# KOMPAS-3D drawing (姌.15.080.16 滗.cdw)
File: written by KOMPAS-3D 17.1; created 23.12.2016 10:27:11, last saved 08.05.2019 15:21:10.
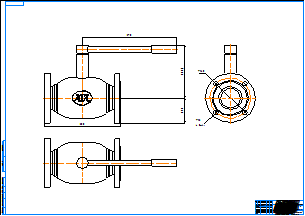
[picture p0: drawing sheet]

Sheet 1: A0, landscape

Title block, sheet 1: name: КШ.15.080.16 фф; material: Внимание! Данный продукт является объектом авторского права ООО «Торговый Дом АДЛ». / Запрещается изменение, копирование, распространение / (в том числе путем копирования на другие сайты и ресурсы в Интернете) / или любое иное использование информации и объектов без предварительного / согласия правообладателя (ООО «Торговый Дом АДЛ»).; sheets: 1; organisation: ООО "Торговый дом АДЛ"; sheet format: A0; stored path: C:\Users\tra\Desktop\2д чертежи\Шаровые краны БИВАЛ\КШ_Бивал_серия_14_15\KOMPAS_2D\КШ.15.080.16 фф.cdw

Views: Вид 1, Проекционный вид 2, Проекционный вид 3
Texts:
  Klimkovich
  ADL
Dimensions and other numbers on the sheet: 300; 370; 205,1; 97,5; 160; 18; 4 Отв.; 1:1; 1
